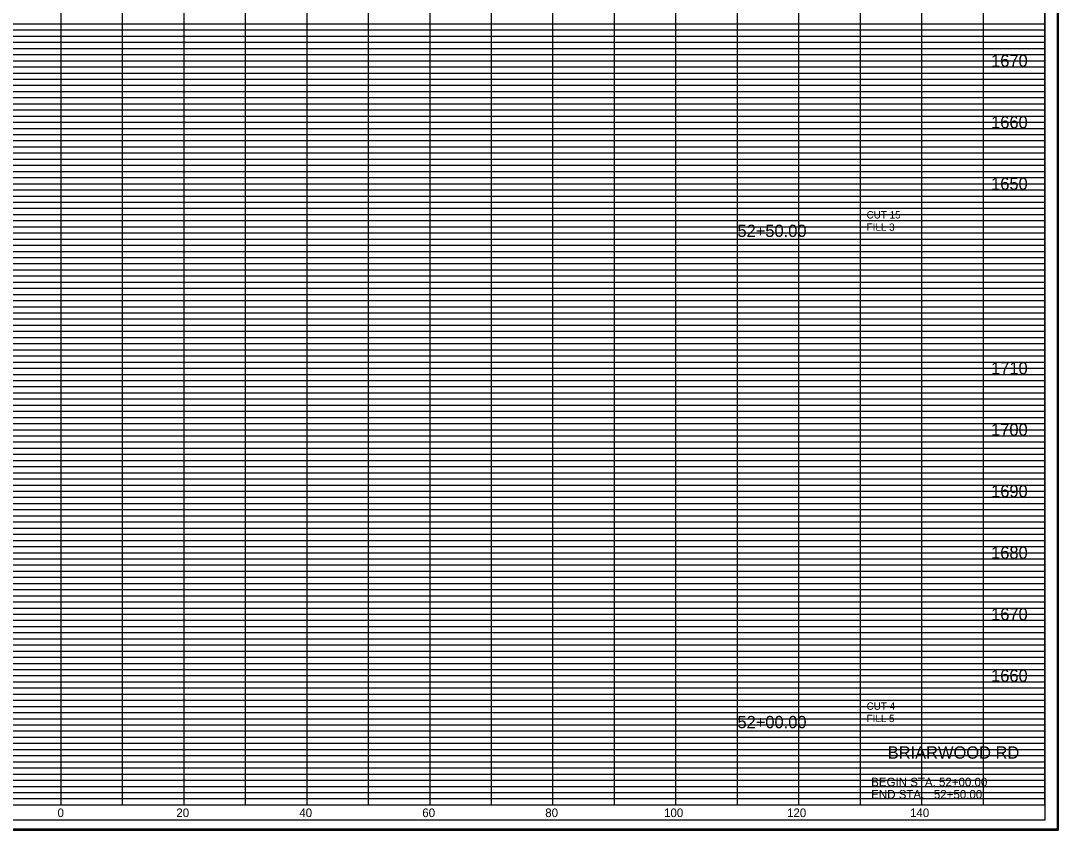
# Model space of a CAD drawing. Extents: x 980 to 2228, y 978 to 2394.
# Drawn here: x 1153.4 to 1322.2, y 1265.9 to 1397.5 of the extents above; entities that cross this region are included whole.
import ezdxf

# ---------------------------------------------------------------- set-up
doc = ezdxf.new("R2010")
doc.units = 0
for name, color, linetype in [('DESIGN - SHEET - Corner Text', 7, 'Continuous'), ('DESIGN - SHEET - Light Grid', 7, 'Continuous'), ('DESIGN - SHEET - Linework', 7, 'Continuous'), ('DESIGN - SHEET - Plot Shape', 7, 'Continuous'), ('DESIGN - TYPICAL - Finished Grade and Subgrade', 7, 'Continuous'), ('DESIGN - TYPICAL - Text', 7, 'Continuous')]:
    doc.layers.add(name, color=color, linetype=linetype)

# ---------------------------------------------------------------- blocks, each defined once
blk = doc.blocks.new('XSTSHT')
at = {"layer": 'DESIGN - SHEET - Light Grid'}
for p, q in [((8, 12.7), (16, 12.7)), ((16, 12.7), (24, 12.7)), ((24, 12.7), (32, 12.7)), ((8, 12.6), (16, 12.6)), ((8, 12.5), (16, 12.5)), ((16, 12.6), (24, 12.6)), ((16, 12.5), (24, 12.5)), ((24, 12.6), (32, 12.6)), ((24, 12.5), (32, 12.5)), ((8, 12.4), (16, 12.4)), ((16, 12.4), (24, 12.4)), ((24, 12.4), (32, 12.4)), ((8, 12.3), (16, 12.3)), ((8, 12.2), (16, 12.2)), ((16, 12.3), (24, 12.3)), ((16, 12.2), (24, 12.2)), ((24, 12.3), (32, 12.3)), ((24, 12.2), (32, 12.2)), ((8, 12.1), (16, 12.1)), ((16, 12.1), (24, 12.1)), ((24, 12.1), (32, 12.1)), ((8, 11.9), (16, 11.9)), ((16, 11.9), (24, 11.9)), ((24, 11.9), (32, 11.9)), ((8, 11.8), (16, 11.8)), ((8, 11.7), (16, 11.7)), ((16, 11.8), (24, 11.8)), ((16, 11.7), (24, 11.7)), ((24, 11.8), (32, 11.8)), ((24, 11.7), (32, 11.7)), ((8, 11.6), (16, 11.6)), ((8, 11.5), (16, 11.5)), ((16, 11.6), (24, 11.6)), ((16, 11.5), (24, 11.5)), ((24, 11.6), (32, 11.6)), ((24, 11.5), (32, 11.5)), ((8, 11.4), (16, 11.4)), ((16, 11.4), (24, 11.4)), ((24, 11.4), (32, 11.4)), ((8, 11.3), (16, 11.3)), ((8, 11.2), (16, 11.2)), ((16, 11.3), (24, 11.3)), ((16, 11.2), (24, 11.2)), ((24, 11.3), (32, 11.3)), ((24, 11.2), (32, 11.2)), ((8, 11.1), (16, 11.1)), ((16, 11.1), (24, 11.1)), ((24, 11.1), (32, 11.1)), ((8, 10.9), (16, 10.9)), ((8, 10.8), (16, 10.8)), ((16, 10.9), (24, 10.9)), ((16, 10.8), (24, 10.8)), ((24, 10.9), (32, 10.9)), ((24, 10.8), (32, 10.8)), ((8, 10.7), (16, 10.7)), ((16, 10.7), (24, 10.7)), ((24, 10.7), (32, 10.7)), ((8, 10.6), (16, 10.6)), ((8, 10.5), (16, 10.5)), ((16, 10.6), (24, 10.6)), ((16, 10.5), (24, 10.5)), ((24, 10.6), (32, 10.6)), ((24, 10.5), (32, 10.5)), ((8, 10.4), (16, 10.4)), ((8, 10.3), (16, 10.3)), ((16, 10.4), (24, 10.4)), ((16, 10.3), (24, 10.3)), ((24, 10.4), (32, 10.4)), ((24, 10.3), (32, 10.3)), ((8, 10.2), (16, 10.2)), ((16, 10.2), (24, 10.2)), ((24, 10.2), (32, 10.2)), ((8, 10.1), (16, 10.1)), ((16, 10.1), (24, 10.1)), ((24, 10.1), (32, 10.1)), ((8, 9.9), (16, 9.9)), ((8, 9.8), (16, 9.8)), ((16, 9.9), (24, 9.9)), ((16, 9.8), (24, 9.8)), ((24, 9.9), (32, 9.9)), ((24, 9.8), (32, 9.8)), ((8, 9.7), (16, 9.7)), ((16, 9.7), (24, 9.7)), ((24, 9.7), (32, 9.7)), ((8, 9.6), (16, 9.6)), ((8, 9.5), (16, 9.5)), ((16, 9.6), (24, 9.6)), ((16, 9.5), (24, 9.5)), ((24, 9.6), (32, 9.6)), ((24, 9.5), (32, 9.5)), ((8, 9.4), (16, 9.4)), ((8, 9.3), (16, 9.3)), ((16, 9.4), (24, 9.4)), ((16, 9.3), (24, 9.3)), ((24, 9.4), (32, 9.4)), ((24, 9.3), (32, 9.3)), ((8, 9.2), (16, 9.2)), ((16, 9.2), (24, 9.2)), ((24, 9.2), (32, 9.2)), ((8, 9.1), (16, 9.1)), ((16, 9.1), (24, 9.1)), ((24, 9.1), (32, 9.1)), ((8, 8.9), (16, 8.9)), ((8, 8.8), (16, 8.8)), ((16, 8.9), (24, 8.9)), ((16, 8.8), (24, 8.8)), ((24, 8.9), (32, 8.9)), ((24, 8.8), (32, 8.8)), ((8, 8.7), (16, 8.7)), ((16, 8.7), (24, 8.7)), ((24, 8.7), (32, 8.7)), ((8, 8.6), (16, 8.6)), ((8, 8.5), (16, 8.5)), ((16, 8.6), (24, 8.6)), ((16, 8.5), (24, 8.5)), ((24, 8.6), (32, 8.6)), ((24, 8.5), (32, 8.5)), ((8, 8.4), (16, 8.4)), ((8, 8.3), (16, 8.3)), ((16, 8.4), (24, 8.4)), ((16, 8.3), (24, 8.3)), ((24, 8.4), (32, 8.4)), ((24, 8.3), (32, 8.3)), ((8, 8.2), (16, 8.2)), ((8, 8.1), (16, 8.1)), ((16, 8.2), (24, 8.2)), ((16, 8.1), (24, 8.1)), ((24, 8.2), (32, 8.2)), ((24, 8.1), (32, 8.1)), ((8, 7.9), (16, 7.9)), ((8, 7.8), (16, 7.8)), ((16, 7.9), (24, 7.9)), ((16, 7.8), (24, 7.8)), ((24, 7.9), (32, 7.9)), ((24, 7.8), (32, 7.8)), ((8, 7.7), (16, 7.7)), ((8, 7.6), (16, 7.6)), ((16, 7.7), (24, 7.7)), ((16, 7.6), (24, 7.6)), ((24, 7.7), (32, 7.7)), ((24, 7.6), (32, 7.6)), ((8, 7.5), (16, 7.5)), ((16, 7.5), (24, 7.5)), ((24, 7.5), (32, 7.5)), ((8, 7.4), (16, 7.4)), ((8, 7.3), (16, 7.3)), ((16, 7.4), (24, 7.4)), ((16, 7.3), (24, 7.3)), ((24, 7.4), (32, 7.4)), ((24, 7.3), (32, 7.3)), ((8, 7.2), (16, 7.2)), ((8, 7.1), (16, 7.1)), ((16, 7.2), (24, 7.2)), ((16, 7.1), (24, 7.1)), ((24, 7.2), (32, 7.2)), ((24, 7.1), (32, 7.1)), ((8, 6.9), (16, 6.9)), ((8, 6.8), (16, 6.8)), ((16, 6.9), (24, 6.9)), ((16, 6.8), (24, 6.8)), ((24, 6.9), (32, 6.9)), ((24, 6.8), (32, 6.8)), ((8, 6.7), (16, 6.7)), ((8, 6.6), (16, 6.6)), ((16, 6.7), (24, 6.7)), ((16, 6.6), (24, 6.6)), ((24, 6.7), (32, 6.7)), ((24, 6.6), (32, 6.6)), ((8, 6.5), (16, 6.5)), ((16, 6.5), (24, 6.5)), ((24, 6.5), (32, 6.5)), ((8, 6.4), (16, 6.4)), ((8, 6.3), (16, 6.3)), ((16, 6.4), (24, 6.4)), ((16, 6.3), (24, 6.3)), ((24, 6.4), (32, 6.4)), ((24, 6.3), (32, 6.3)), ((8, 6.2), (16, 6.2)), ((8, 6.1), (16, 6.1)), ((16, 6.2), (24, 6.2)), ((16, 6.1), (24, 6.1)), ((24, 6.2), (32, 6.2)), ((24, 6.1), (32, 6.1)), ((8, 5.9), (16, 5.9)), ((8, 5.8), (16, 5.8)), ((16, 5.9), (24, 5.9)), ((16, 5.8), (24, 5.8)), ((24, 5.9), (32, 5.9)), ((24, 5.8), (32, 5.8)), ((8, 5.7), (16, 5.7)), ((8, 5.6), (16, 5.6)), ((16, 5.7), (24, 5.7)), ((16, 5.6), (24, 5.6)), ((24, 5.7), (32, 5.7)), ((24, 5.6), (32, 5.6)), ((8, 5.5), (16, 5.5)), ((8, 5.4), (16, 5.4)), ((16, 5.5), (24, 5.5)), ((16, 5.4), (24, 5.4)), ((24, 5.5), (32, 5.5)), ((24, 5.4), (32, 5.4)), ((8, 5.3), (16, 5.3)), ((16, 5.3), (24, 5.3)), ((24, 5.3), (32, 5.3)), ((8, 5.2), (16, 5.2)), ((8, 5.1), (16, 5.1)), ((16, 5.2), (24, 5.2)), ((16, 5.1), (24, 5.1)), ((24, 5.2), (32, 5.2)), ((24, 5.1), (32, 5.1)), ((8, 4.9), (16, 4.9)), ((16, 4.9), (24, 4.9)), ((24, 4.9), (32, 4.9)), ((8, 4.8), (16, 4.8)), ((16, 4.8), (24, 4.8)), ((24, 4.8), (32, 4.8)), ((8, 4.7), (16, 4.7)), ((8, 4.6), (16, 4.6)), ((16, 4.7), (24, 4.7)), ((16, 4.6), (24, 4.6)), ((24, 4.7), (32, 4.7)), ((24, 4.6), (32, 4.6)), ((8, 4.5), (16, 4.5)), ((8, 4.4), (16, 4.4)), ((16, 4.5), (24, 4.5)), ((16, 4.4), (24, 4.4)), ((24, 4.5), (32, 4.5)), ((24, 4.4), (32, 4.4)), ((8, 4.3), (16, 4.3)), ((16, 4.3), (24, 4.3)), ((24, 4.3), (32, 4.3)), ((8, 4.2), (16, 4.2)), ((8, 4.1), (16, 4.1)), ((16, 4.2), (24, 4.2)), ((16, 4.1), (24, 4.1)), ((24, 4.2), (32, 4.2)), ((24, 4.1), (32, 4.1)), ((8, 3.9), (16, 3.9)), ((16, 3.9), (24, 3.9)), ((24, 3.9), (32, 3.9)), ((8, 3.8), (16, 3.8)), ((16, 3.8), (24, 3.8)), ((24, 3.8), (32, 3.8)), ((8, 3.7), (16, 3.7)), ((8, 3.6), (16, 3.6)), ((16, 3.7), (24, 3.7)), ((16, 3.6), (24, 3.6)), ((24, 3.7), (32, 3.7)), ((24, 3.6), (32, 3.6)), ((8, 3.5), (16, 3.5)), ((8, 3.4), (16, 3.4)), ((16, 3.5), (24, 3.5)), ((16, 3.4), (24, 3.4)), ((24, 3.5), (32, 3.5)), ((24, 3.4), (32, 3.4)), ((8, 3.3), (16, 3.3)), ((16, 3.3), (24, 3.3)), ((24, 3.3), (32, 3.3)), ((8, 3.2), (16, 3.2)), ((8, 3.1), (16, 3.1)), ((16, 3.2), (24, 3.2)), ((16, 3.1), (24, 3.1)), ((24, 3.2), (32, 3.2)), ((24, 3.1), (32, 3.1)), ((8, 2.9), (16, 2.9)), ((16, 2.9), (24, 2.9)), ((24, 2.9), (32, 2.9)), ((8, 2.8), (16, 2.8)), ((8, 2.7), (16, 2.7)), ((16, 2.8), (24, 2.8)), ((16, 2.7), (24, 2.7)), ((24, 2.8), (32, 2.8)), ((24, 2.7), (32, 2.7)), ((8, 2.6), (16, 2.6)), ((16, 2.6), (24, 2.6)), ((24, 2.6), (32, 2.6)), ((8, 2.5), (16, 2.5)), ((8, 2.4), (16, 2.4)), ((16, 2.5), (24, 2.5)), ((16, 2.4), (24, 2.4)), ((24, 2.5), (32, 2.5)), ((24, 2.4), (32, 2.4)), ((8, 2.3), (16, 2.3)), ((8, 2.2), (16, 2.2)), ((16, 2.3), (24, 2.3)), ((16, 2.2), (24, 2.2)), ((24, 2.3), (32, 2.3)), ((24, 2.2), (32, 2.2)), ((8, 2.1), (16, 2.1)), ((16, 2.1), (24, 2.1)), ((24, 2.1), (32, 2.1)), ((8, 1.9), (16, 1.9)), ((16, 1.9), (24, 1.9)), ((24, 1.9), (32, 1.9)), ((8, 1.8), (16, 1.8)), ((8, 1.7), (16, 1.7)), ((16, 1.8), (24, 1.8)), ((16, 1.7), (24, 1.7)), ((24, 1.8), (32, 1.8)), ((24, 1.7), (32, 1.7)), ((8, 1.6), (16, 1.6)), ((16, 1.6), (24, 1.6)), ((24, 1.6), (32, 1.6)), ((8, 1.5), (16, 1.5)), ((8, 1.4), (16, 1.4)), ((16, 1.5), (24, 1.5)), ((16, 1.4), (24, 1.4)), ((24, 1.5), (32, 1.5)), ((24, 1.4), (32, 1.4)), ((8, 1.3), (16, 1.3)), ((8, 1.2), (16, 1.2)), ((16, 1.3), (24, 1.3)), ((16, 1.2), (24, 1.2)), ((24, 1.3), (32, 1.3)), ((24, 1.2), (32, 1.2)), ((8, 1.1), (16, 1.1)), ((16, 1.1), (24, 1.1)), ((24, 1.1), (32, 1.1)), ((8, 0.9), (16, 0.9)), ((16, 0.9), (24, 0.9)), ((24, 0.9), (32, 0.9)), ((8, 0.8), (16, 0.8)), ((8, 0.7), (16, 0.7)), ((16, 0.8), (24, 0.8)), ((16, 0.7), (24, 0.7)), ((24, 0.8), (32, 0.8)), ((24, 0.7), (32, 0.7)), ((8, 0.6), (16, 0.6)), ((16, 0.6), (24, 0.6)), ((24, 0.6), (32, 0.6)), ((8, 0.5), (16, 0.5)), ((8, 0.4), (16, 0.4)), ((16, 0.5), (24, 0.5)), ((16, 0.4), (24, 0.4)), ((24, 0.5), (32, 0.5)), ((24, 0.4), (32, 0.4)), ((8, 0.3), (16, 0.3)), ((8, 0.2), (16, 0.2)), ((16, 0.3), (24, 0.3)), ((16, 0.2), (24, 0.2)), ((24, 0.3), (32, 0.3)), ((24, 0.2), (32, 0.2)), ((8, 0.1), (16, 0.1)), ((16, 0.1), (24, 0.1)), ((24, 0.1), (32, 0.1))]:
    blk.add_line(p, q, dxfattribs=at)
at = {"layer": 'DESIGN - SHEET - Linework'}
for p, q in [((32.217, 21.414), (32.217, -0.414)), ((16, 0), (16, 21)), ((17, 0), (17, 21)), ((18, 0), (18, 21)), ((19, 0), (19, 21)), ((20, 0), (20, 21)), ((21, 0), (21, 21)), ((22, 0), (22, 21)), ((23, 0), (23, 21)), ((24, 0), (24, 21)), ((25, 0), (25, 21)), ((26, 0), (26, 21)), ((27, 0), (27, 21)), ((28, 0), (28, 20)), ((29, 0), (29, 20)), ((30, 0), (30, 20)), ((31, 0), (31, 20)), ((0, 12), (32, 12)), ((0, 11), (32, 11)), ((0, 10), (32, 10)), ((0, 9), (32, 9)), ((0, 8), (32, 8)), ((0, 7), (32, 7)), ((0, 6), (32, 6)), ((0, 5), (32, 5)), ((0, 4), (32, 4)), ((0, 3), (32, 3)), ((0, 2), (32, 2)), ((0, 1), (32, 1)), ((-1.823, -0.414), (32.217, -0.414))]:
    blk.add_line(p, q, dxfattribs=at)
blk.add_lwpolyline([(0, 21), (0, 0), (32, 0), (32, 21), (0, 21)], dxfattribs=at)
at = {"layer": 'DESIGN - SHEET - Plot Shape'}
for points in [[(-1.803, 21.394), (32.197, 21.394), (32.197, -0.394), (-1.803, -0.394)], [(-0.85, 21), (32, 21), (32, -0.25), (-0.85, -0.25)]]:
    blk.add_lwpolyline(points, close=True, dxfattribs=at)

msp = doc.modelspace()

# ---------------------------------------------------------------- linework, layer by layer
at = {"layer": 'DESIGN - SHEET - Plot Shape'}
msp.add_lwpolyline([(991.5, 1480), (1320, 1480), (1320, 1267.5), (991.5, 1267.5)], close=True, dxfattribs=at)

# ---------------------------------------------------------------- block references
at = {"layer": 'DESIGN - TYPICAL - Finished Grade and Subgrade', "xscale": 10, "yscale": 10}
msp.add_blockref('XSTSHT', (1000, 1270), dxfattribs=at)

# ---------------------------------------------------------------- texts
at = {"layer": 'DESIGN - SHEET - Corner Text'}
for s, height, p in [('1670', 2, (1311.25, 1390)), ('1660', 2, (1311.25, 1380)), ('1650', 2, (1311.25, 1370)), ('1710', 2, (1311.25, 1340)), ('1700', 2, (1311.25, 1330)), ('1690', 2, (1311.25, 1320)), ('1680', 2, (1311.25, 1310)), ('1670', 2, (1311.25, 1300)), ('1660', 2, (1311.25, 1290)), ('BRIARWOOD RD', 2, (1294.44, 1277.5)), ('BEGIN STA. 52+00.00', 1.4, (1291.75, 1273)), ('END STA.   52+50.00', 1.4, (1291.75, 1271)), ('0', 1.4, (1159.42, 1268)), ('0', 1.4, (1159.42, 1268)), ('20', 1.4, (1178.74, 1268)), ('40', 1.4, (1198.74, 1268)), ('60', 1.4, (1218.74, 1268)), ('80', 1.4, (1238.74, 1268)), ('100', 1.4, (1258.06, 1268)), ('120', 1.4, (1278.06, 1268)), ('140', 1.4, (1298.06, 1268))]:
    msp.add_text(s, height=height, dxfattribs=at).set_placement(p)
at = {"layer": 'DESIGN - TYPICAL - Text'}
for s, height, p in [('CUT 15', 1.2, (1291, 1365.34)), ('52+50.00', 2, (1270, 1362.34)), ('FILL 3', 1.2, (1291, 1363.34)), ('CUT 4', 1.2, (1291, 1285.45)), ('52+00.00', 2, (1270, 1282.45)), ('FILL 5', 1.2, (1291, 1283.45))]:
    msp.add_text(s, height=height, dxfattribs=at).set_placement(p)

doc.saveas('drawing.dxf')
